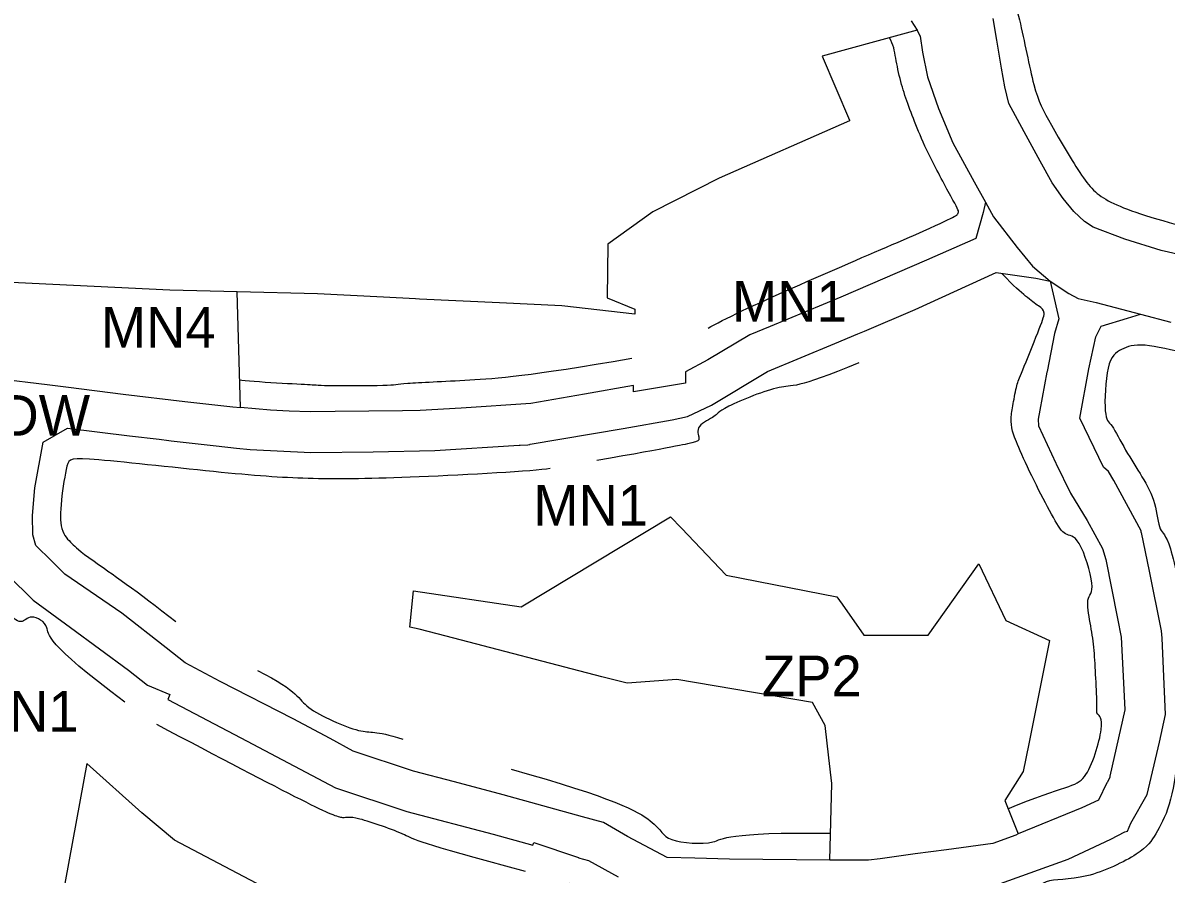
# Model space of a CAD drawing. Extents: x 7413438 to 7416393, y 5541665 to 5544118.
# Drawn here: x 7414274.3 to 7414442.9, y 5542946.8 to 5543072.4 of the extents above; entities that cross this region are included whole.
import ezdxf

# ---------------------------------------------------------------- set-up
doc = ezdxf.new("R2010")
doc.units = 0
for name, color, linetype in [('linie_rozgraniczajace', 7, 'Continuous'), ('linie_zabudowy_nieprzekraczalne', 7, 'Continuous'), ('oznaczenia_przeznaczen', 7, 'Continuous')]:
    doc.layers.add(name, color=color, linetype=linetype)

msp = doc.modelspace()

# ---------------------------------------------------------------- linework, layer by layer
at = {"layer": 'linie_rozgraniczajace'}
for p, q in [((7414405.28, 5543072.75), (7414406.15, 5543071.36)), ((7414417.91, 5543069.9), (7414417.38, 5543073.07)), ((7414403.99, 5543070.78), (7414392.16, 5543067.52)), ((7414406.15, 5543071.36), (7414403.99, 5543070.79)), ((7414403.99, 5543070.79), (7414403.99, 5543070.78)), ((7414406.15, 5543071.36), (7414406.58, 5543070.55)), ((7414406.58, 5543070.55), (7414406.61, 5543070.53)), ((7414406.61, 5543070.53), (7414406.61, 5543070.49)), ((7414406.61, 5543070.49), (7414406.93, 5543068.13)), ((7414418.6, 5543065.77), (7414417.91, 5543069.9)), ((7414392.16, 5543067.52), (7414396.16, 5543058.08)), ((7414406.93, 5543068.13), (7414407.67, 5543064.49)), ((7414419.07, 5543062.99), (7414418.6, 5543065.77)), ((7414407.67, 5543064.49), (7414409.33, 5543059.8)), ((7414419.68, 5543060.56), (7414419.07, 5543062.99)), ((7414421.92, 5543056.39), (7414419.68, 5543060.56)), ((7414409.33, 5543059.8), (7414411.44, 5543054.76)), ((7414396.16, 5543057.97), (7414376.95, 5543049.52)), ((7414396.16, 5543058.08), (7414396.16, 5543057.97)), ((7414424.31, 5543052.04), (7414421.92, 5543056.39)), ((7414411.44, 5543054.76), (7414414.55, 5543049.01)), ((7414426.09, 5543048.82), (7414424.31, 5543052.04)), ((7414376.95, 5543049.52), (7414367.18, 5543044.55)), ((7414414.55, 5543049.01), (7414416.22, 5543046)), ((7414427.67, 5543046.52), (7414426.09, 5543048.82)), ((7414429.28, 5543044.6), (7414427.67, 5543046.52)), ((7414416.22, 5543046), (7414415.92, 5543044.48)), ((7414416.22, 5543046), (7414417.42, 5543043.83)), ((7414367.18, 5543044.55), (7414360.55, 5543039.78)), ((7414415.92, 5543044.48), (7414414.81, 5543040.61)), ((7414417.42, 5543043.83), (7414420.89, 5543039.32)), ((7414430.85, 5543043.12), (7414429.28, 5543044.6)), ((7414432.11, 5543042.3), (7414430.85, 5543043.12)), ((7414436.79, 5543040.53), (7414432.11, 5543042.3)), ((7414360.55, 5543039.78), (7414360.46, 5543031.86)), ((7414414.81, 5543040.61), (7414407.55, 5543037.43)), ((7414442.16, 5543038.85), (7414436.79, 5543040.53)), ((7414420.89, 5543039.32), (7414423.15, 5543036.56)), ((7414468.63, 5543032.8), (7414442.16, 5543038.85)), ((7414407.55, 5543037.43), (7414394.92, 5543031.99)), ((7414423.15, 5543036.56), (7414425.77, 5543034.34)), ((7414295.95, 5543033.02), (7414248.57, 5543035.32)), ((7414405.89, 5543030.16), (7414417.81, 5543035.62)), ((7414417.81, 5543035.62), (7414423.64, 5543034.8)), ((7414423.64, 5543034.8), (7414425.77, 5543034.34)), ((7414305.88, 5543032.74), (7414295.95, 5543033.02)), ((7414425.77, 5543034.34), (7414426.05, 5543033.03)), ((7414425.77, 5543034.34), (7414428.53, 5543032.49)), ((7414426.05, 5543033.03), (7414427.05, 5543028.77)), ((7414306.35, 5543015.7), (7414305.88, 5543032.74)), ((7414317.73, 5543032.46), (7414305.88, 5543032.74)), ((7414327.47, 5543031.97), (7414317.73, 5543032.46)), ((7414332.2, 5543031.73), (7414327.47, 5543031.97)), ((7414332.77, 5543031.7), (7414332.2, 5543031.73)), ((7414344.56, 5543031.15), (7414332.77, 5543031.7)), ((7414360.46, 5543031.86), (7414364.53, 5543030.2)), ((7414394.92, 5543031.99), (7414384.49, 5543027.65)), ((7414428.53, 5543032.49), (7414429.89, 5543031.78)), ((7414429.89, 5543031.78), (7414432.56, 5543031.19)), ((7414353.77, 5543030.71), (7414344.56, 5543031.15)), ((7414364.51, 5543029.45), (7414353.77, 5543030.71)), ((7414364.53, 5543030.2), (7414364.51, 5543029.45)), ((7414398.39, 5543026.97), (7414405.89, 5543030.16)), ((7414432.56, 5543031.19), (7414439.11, 5543029.46)), ((7414427.05, 5543028.77), (7414426.42, 5543026.6)), ((7414433.31, 5543027.68), (7414437.19, 5543028.88)), ((7414437.19, 5543028.88), (7414439.11, 5543029.46)), ((7414439.11, 5543029.46), (7414443.55, 5543028.29)), ((7414381.5, 5543026.4), (7414375.3, 5543022.71)), ((7414384.49, 5543027.65), (7414381.5, 5543026.4)), ((7414394.04, 5543025.13), (7414397.42, 5543026.56)), ((7414397.42, 5543026.56), (7414398.39, 5543026.97)), ((7414426.42, 5543026.6), (7414425.33, 5543020.98)), ((7414432.53, 5543026.14), (7414433.31, 5543027.68)), ((7414384.11, 5543020.99), (7414394.04, 5543025.13)), ((7414431.5, 5543021.4), (7414432.53, 5543026.14)), ((7414375.3, 5543022.71), (7414372, 5543020.95)), ((7414430.13, 5543014.11), (7414431.5, 5543021.4)), ((7414267.9, 5543020.3), (7414277.85, 5543019.08)), ((7414372, 5543020.95), (7414372.01, 5543019.29)), ((7414375.84, 5543016.05), (7414384.11, 5543020.99)), ((7414425.3, 5543020.91), (7414424.25, 5543015.32)), ((7414425.33, 5543020.98), (7414425.3, 5543020.91)), ((7414277.85, 5543019.08), (7414281.03, 5543018.68)), ((7414281.03, 5543018.68), (7414289.06, 5543017.67)), ((7414364.31, 5543018.94), (7414357.11, 5543017.67)), ((7414364.32, 5543017.98), (7414364.31, 5543018.94)), ((7414372.01, 5543019.29), (7414364.32, 5543017.98)), ((7414289.06, 5543017.67), (7414298.17, 5543016.57)), ((7414298.17, 5543016.57), (7414305.23, 5543015.79)), ((7414349.18, 5543016.27), (7414338.91, 5543015.6)), ((7414357.11, 5543017.67), (7414349.18, 5543016.27)), ((7414305.23, 5543015.79), (7414306.35, 5543015.67)), ((7414310.82, 5543015.3), (7414306.35, 5543015.7)), ((7414306.35, 5543015.67), (7414306.35, 5543015.7)), ((7414313.55, 5543015.17), (7414310.82, 5543015.3)), ((7414316.65, 5543015.06), (7414313.55, 5543015.17)), ((7414320.33, 5543015.1), (7414316.65, 5543015.06)), ((7414330.25, 5543015.21), (7414320.33, 5543015.1)), ((7414332.88, 5543015.27), (7414330.25, 5543015.21)), ((7414338.91, 5543015.6), (7414332.88, 5543015.25)), ((7414332.88, 5543015.25), (7414332.88, 5543015.27)), ((7414372.31, 5543014.36), (7414375.84, 5543016.05)), ((7414424.25, 5543015.32), (7414424.01, 5543013.98)), ((7414362.81, 5543012.58), (7414370.02, 5543013.86)), ((7414370.02, 5543013.89), (7414372.31, 5543014.36)), ((7414370.02, 5543013.86), (7414370.02, 5543013.89)), ((7414424.01, 5543013.98), (7414424.08, 5543013.01)), ((7414424.08, 5543013.01), (7414426.59, 5543007.5)), ((7414433.62, 5543006.9), (7414430.13, 5543014.11)), ((7414277.25, 5543010.56), (7414280.84, 5543012.66)), ((7414280.84, 5543012.66), (7414290.02, 5543011.5)), ((7414290.02, 5543011.5), (7414294.36, 5543011)), ((7414349.1, 5543010.26), (7414362.81, 5543012.58)), ((7414276.05, 5543003.83), (7414277.25, 5543010.56)), ((7414294.36, 5543011), (7414295.81, 5543010.8)), ((7414295.81, 5543010.8), (7414296.17, 5543010.79)), ((7414296.17, 5543010.79), (7414302.76, 5543010.03)), ((7414302.76, 5543010.03), (7414305.79, 5543009.7)), ((7414305.79, 5543009.7), (7414307.82, 5543009.47)), ((7414307.82, 5543009.47), (7414316.73, 5543009.06)), ((7414335.04, 5543009.34), (7414347.45, 5543010.14)), ((7414347.45, 5543010.14), (7414347.63, 5543010.15)), ((7414347.63, 5543010.15), (7414348.76, 5543010.17)), ((7414348.76, 5543010.17), (7414349.06, 5543010.25)), ((7414349.06, 5543010.25), (7414349.1, 5543010.26)), ((7414316.73, 5543009.06), (7414325.96, 5543009.16)), ((7414325.96, 5543009.16), (7414335.04, 5543009.34)), ((7414426.59, 5543007.5), (7414426.63, 5543007.5)), ((7414426.63, 5543007.5), (7414426.64, 5543007.39)), ((7414426.64, 5543007.39), (7414428.77, 5543003.06)), ((7414434.38, 5543006.23), (7414433.62, 5543006.9)), ((7414435.16, 5543004.91), (7414434.38, 5543006.23)), ((7414439.18, 5542997.47), (7414435.16, 5543004.91)), ((7414275.72, 5542999.78), (7414276.05, 5543003.83)), ((7414428.77, 5543003.06), (7414431.21, 5542999)), ((7414275.73, 5542996.9), (7414275.72, 5542999.78)), ((7414347.76, 5542986.3), (7414369.81, 5542999.57)), ((7414369.81, 5542999.57), (7414371.41, 5542997.89)), ((7414371.41, 5542997.89), (7414371.41, 5542997.88)), ((7414371.41, 5542997.88), (7414378.01, 5542990.97)), ((7414431.21, 5542999), (7414433.49, 5542994.9)), ((7414276.17, 5542995.35), (7414275.73, 5542996.9)), ((7414439.22, 5542997.26), (7414439.18, 5542997.47)), ((7414439.23, 5542997.26), (7414439.22, 5542997.26)), ((7414440.45, 5542991.55), (7414439.23, 5542997.26)), ((7414278.48, 5542993.06), (7414276.17, 5542995.35)), ((7414433.49, 5542994.9), (7414433.99, 5542993.25)), ((7414280.46, 5542991.09), (7414278.48, 5542993.06)), ((7414407.77, 5542982.08), (7414415.24, 5542992.61)), ((7414415.24, 5542992.61), (7414419.22, 5542984.24)), ((7414433.99, 5542993.25), (7414435.71, 5542984.56)), ((7414272.07, 5542990.97), (7414275.78, 5542987.28)), ((7414282.32, 5542989.82), (7414280.46, 5542991.09)), ((7414378.01, 5542990.97), (7414394.32, 5542987.76)), ((7414442.18, 5542982.74), (7414440.45, 5542991.55)), ((7414288.88, 5542985.35), (7414282.32, 5542989.82)), ((7414331.35, 5542983.26), (7414331.89, 5542988.65)), ((7414331.89, 5542988.65), (7414347.76, 5542986.3)), ((7414394.32, 5542987.76), (7414395.08, 5542986.69)), ((7414275.78, 5542987.28), (7414281.31, 5542983.24)), ((7414395.08, 5542986.69), (7414398.31, 5542982.12)), ((7414295.39, 5542980.21), (7414288.88, 5542985.35)), ((7414419.22, 5542984.24), (7414425.7, 5542981.32)), ((7414435.71, 5542984.56), (7414436.25, 5542981.79)), ((7414281.31, 5542983.24), (7414289.84, 5542976.95)), ((7414332.73, 5542982.99), (7414331.35, 5542983.26)), ((7414336.69, 5542981.95), (7414332.73, 5542982.99)), ((7414442.27, 5542981.64), (7414442.18, 5542982.74)), ((7414359.65, 5542975.94), (7414336.69, 5542981.95)), ((7414398.31, 5542982.12), (7414404.1, 5542982.1)), ((7414404.1, 5542982.1), (7414407.77, 5542982.08)), ((7414425.7, 5542981.32), (7414422.62, 5542966.07)), ((7414436.25, 5542981.79), (7414436.65, 5542974.09)), ((7414442.5, 5542977.14), (7414442.27, 5542981.64)), ((7414298.19, 5542978), (7414295.39, 5542980.21)), ((7414303.35, 5542975.26), (7414298.19, 5542978)), ((7414289.84, 5542976.95), (7414292.65, 5542974.73)), ((7414363.38, 5542975.02), (7414359.65, 5542975.94)), ((7414442.79, 5542970.38), (7414442.5, 5542977.14)), ((7414292.65, 5542974.73), (7414295.95, 5542973.33)), ((7414314.12, 5542969.76), (7414303.35, 5542975.26)), ((7414370.71, 5542975.54), (7414363.38, 5542975.02)), ((7414390.75, 5542972.15), (7414370.71, 5542975.54)), ((7414436.65, 5542974.09), (7414436.81, 5542971.1)), ((7414295.95, 5542973.33), (7414295.65, 5542972.61)), ((7414295.65, 5542972.61), (7414306.4, 5542966.97)), ((7414392.59, 5542968.77), (7414390.75, 5542972.15)), ((7414436.81, 5542971.1), (7414434.6, 5542961.28)), ((7414319.59, 5542966.83), (7414314.12, 5542969.76)), ((7414441.89, 5542966.33), (7414442.79, 5542970.38)), ((7414393.15, 5542964.01), (7414392.59, 5542968.77)), ((7414306.4, 5542966.97), (7414320.37, 5542959.59)), ((7414322.99, 5542964.99), (7414319.59, 5542966.83)), ((7414422.62, 5542966.07), (7414421.79, 5542961.97)), ((7414440.09, 5542958.57), (7414441.89, 5542966.33)), ((7414331.89, 5542962.04), (7414322.99, 5542964.99)), ((7414393.59, 5542960.19), (7414393.15, 5542964.01)), ((7414283.71, 5542963.14), (7414278.97, 5542937.43)), ((7414283.72, 5542963.16), (7414283.71, 5542963.14)), ((7414291.83, 5542955.9), (7414283.72, 5542963.16)), ((7414337.93, 5542960.44), (7414331.89, 5542962.04)), ((7414421.79, 5542961.97), (7414419.09, 5542957.71)), ((7414434.57, 5542961.11), (7414434.17, 5542960.34)), ((7414434.6, 5542961.28), (7414434.57, 5542961.11)), ((7414320.37, 5542959.59), (7414330.91, 5542956.09)), ((7414345.12, 5542958.53), (7414337.93, 5542960.44)), ((7414393.28, 5542948.92), (7414393.59, 5542960.19)), ((7414434.13, 5542960.3), (7414432.91, 5542957.77)), ((7414434.17, 5542960.34), (7414434.13, 5542960.3)), ((7414356.83, 5542955.3), (7414345.12, 5542958.53)), ((7414419.09, 5542957.71), (7414421.08, 5542952.76)), ((7414432.91, 5542957.77), (7414430.43, 5542956.62)), ((7414437.68, 5542954.35), (7414440.09, 5542958.57)), ((7414296.63, 5542951.86), (7414291.83, 5542955.9)), ((7414330.91, 5542956.09), (7414343.62, 5542952.72)), ((7414430.43, 5542956.62), (7414421.08, 5542952.76)), ((7414359.89, 5542954.44), (7414356.83, 5542955.3)), ((7414363.46, 5542952.41), (7414359.89, 5542954.44)), ((7414437.17, 5542953.18), (7414437.68, 5542954.35)), ((7414343.62, 5542952.72), (7414349.5, 5542951.1)), ((7414369.27, 5542949.28), (7414363.46, 5542952.41)), ((7414420.7, 5542952.6), (7414417.32, 5542951.35)), ((7414421.08, 5542952.76), (7414420.7, 5542952.6)), ((7414434.74, 5542952.01), (7414436.8, 5542953.07)), ((7414436.8, 5542953.07), (7414437.17, 5542953.18)), ((7414296.63, 5542951.85), (7414296.63, 5542951.86)), ((7414325.17, 5542936.87), (7414296.63, 5542951.85)), ((7414349.5, 5542951.1), (7414349.64, 5542951.52)), ((7414349.64, 5542951.52), (7414356.23, 5542949.3)), ((7414410.49, 5542950.43), (7414405.88, 5542949.81)), ((7414417.32, 5542951.35), (7414410.49, 5542950.43)), ((7414428.42, 5542949.06), (7414434.74, 5542952.01)), ((7414356.23, 5542949.3), (7414356.21, 5542949.25)), ((7414356.21, 5542949.25), (7414357.68, 5542948.84)), ((7414357.68, 5542948.84), (7414362.05, 5542946.44)), ((7414373.39, 5542949.18), (7414369.27, 5542949.28)), ((7414378.5, 5542949.05), (7414373.39, 5542949.18)), ((7414393.27, 5542948.92), (7414378.5, 5542949.05)), ((7414393.28, 5542948.92), (7414393.27, 5542948.92)), ((7414396.5, 5542948.9), (7414393.28, 5542948.92)), ((7414398.98, 5542948.88), (7414396.5, 5542948.9)), ((7414400.69, 5542949.11), (7414398.98, 5542948.88)), ((7414405.88, 5542949.81), (7414400.69, 5542949.11)), ((7414418.45, 5542945.45), (7414428.42, 5542949.06))]:
    msp.add_line(p, q, dxfattribs=at)
at = {"layer": 'linie_zabudowy_nieprzekraczalne'}
for points in [[(7414431.95, 5543087.28), (7414424.23, 5543086.19), (7414420.06, 5543085.34), (7414419, 5543080.42), (7414421.28, 5543073.71), (7414423.39, 5543062.01), (7414425.39, 5543058.29), (7414430.81, 5543048.92), (7414433.87, 5543045.88), (7414444.69, 5543042.35), (7414474.63, 5543035.39), (7414481.89, 5543033.43), (7414483.16, 5543036.96), (7414485.08, 5543039.86), (7414490.96, 5543045.85), (7414497.7, 5543051.64), (7414500.63, 5543053.95), (7414503, 5543055.91), (7414505.09, 5543056.77), (7414509.77, 5543055.9), (7414530.22, 5543051.06), (7414537.37, 5543048.9), (7414539.27, 5543048.01), (7414540.33, 5543046.71), (7414543.6, 5543045.77), (7414547.8, 5543044.76), (7414549.47, 5543044.91), (7414562.64, 5543048.9), (7414579.93, 5543054.1), (7414600, 5543060.19), (7414616.25, 5543065.09), (7414646.94, 5543074.37), (7414667.99, 5543080.68), (7414683.48, 5543085.15), (7414703.27, 5543094.8), (7414711.92, 5543099.17), (7414719.64, 5543105.12), (7414735.49, 5543119.82), (7414750.36, 5543133.73), (7414756.76, 5543139.86), (7414758.13, 5543140.61), (7414759.94, 5543140.74), (7414761.63, 5543140.06), (7414763.36, 5543138.3), (7414765.4, 5543135.79), (7414765.75, 5543133.75), (7414763.94, 5543132.46), (7414737.28, 5543107.58), (7414725.35, 5543096.6), (7414718.45, 5543091.83), (7414705.59, 5543084.52), (7414694.22, 5543079.04), (7414682.4, 5543074.49), (7414654.76, 5543066.06), (7414598.61, 5543048.77), (7414574.71, 5543041.85)], [(7414375.32, 5543027.39), (7414379.54, 5543029.9), (7414410.74, 5543043.2), (7414412.55, 5543044.32), (7414412.05, 5543045.17), (7414407.88, 5543052.85), (7414406.1, 5543057.02), (7414404.74, 5543060.62), (7414403.7, 5543063.68), (7414402.94, 5543067.43), (7414402.69, 5543069.24), (7414402.07, 5543070.25)], [(7414419.52, 5542956.49), (7414428.17, 5542960.01), (7414431.05, 5542959.28), (7414434.05, 5542969.84), (7414432.49, 5542970.33), (7414432.74, 5542971.42), (7414432.47, 5542976.5), (7414432.27, 5542980.39), (7414431.73, 5542983.81), (7414430.93, 5542987.86), (7414432.67, 5542988.43), (7414429.95, 5542997.17), (7414427.96, 5542996.51), (7414426.48, 5542999), (7414423.72, 5543004.14), (7414421.09, 5543009.81), (7414420.09, 5543012.31), (7414419.96, 5543014.07), (7414420.27, 5543016.04), (7414420.89, 5543019.32), (7414421.3, 5543020.15), (7414424.29, 5543027.55), (7414425.2, 5543029.9), (7414424.2, 5543030.53), (7414422.29, 5543032), (7414420.51, 5543033.5), (7414418.67, 5543035.48)], [(7414508.57, 5543008.49), (7414498.05, 5543011.01), (7414482.82, 5543014.57), (7414466.45, 5543018.77), (7414466.58, 5543021.39), (7414454.91, 5543021.58), (7414446.03, 5543023.6), (7414439.09, 5543025.32), (7414436.2, 5543024.38), (7414434.02, 5543022.75), (7414433.67, 5543013.7), (7414434.74, 5543013.63), (7414436.82, 5543009.35), (7414439.42, 5543005.48), (7414441.42, 5543001.64), (7414441.84, 5542997.01), (7414443.29, 5542997.15), (7414446.06, 5542983.5), (7414446.66, 5542972.27), (7414444.62, 5542972.19), (7414444.71, 5542964.02), (7414443.51, 5542956.57), (7414441.21, 5542952.53), (7414439.68, 5542950.09), (7414430.8, 5542945.76), (7414424.13, 5542946.32), (7414423.85, 5542943.15), (7414419.34, 5542941.55), (7414419.25, 5542942.16), (7414410.29, 5542941.57), (7414410.19, 5542942.53), (7414398.73, 5542941.28), (7414399.01, 5542938.87), (7414386.65, 5542938.96), (7414386.72, 5542941.47), (7414376.67, 5542941.82), (7414376.65, 5542941.2), (7414372.17, 5542941.36), (7414372.04, 5542937.46), (7414368.78, 5542927.14), (7414366.7, 5542919.38), (7414363.5, 5542919.82), (7414362.16, 5542913.25), (7414361.63, 5542910.64), (7414365.18, 5542909.93), (7414363.25, 5542893.09), (7414363.14, 5542890.51), (7414361.23, 5542890.49), (7414360.59, 5542881.54), (7414370.8, 5542880.96), (7414377.49, 5542880.26)], [(7414364.1, 5543022.92), (7414348.65, 5543020.23), (7414339.68, 5543019.65), (7414329.31, 5543019.19), (7414329.33, 5543018.87), (7414317.5, 5543018.87), (7414317.28, 5543019.05), (7414311.04, 5543019.27), (7414306.18, 5543019.71), (7414306.17, 5543019.72)], [(7414397.55, 5543022.28), (7414388.1, 5543018.33), (7414387.47, 5543019.75), (7414376.5, 5543015.25), (7414376.82, 5543014.46), (7414373.33, 5543013.03), (7414374.21, 5543010.85), (7414373.69, 5543010.62), (7414370.31, 5543009.87), (7414358.94, 5543007.86)], [(7414289.31, 5542972.21), (7414277.42, 5542981.08), (7414278.75, 5542983.47), (7414275.17, 5542985.42), (7414274.19, 5542983.43), (7414271.84, 5542985.48), (7414268.18, 5542989.26), (7414266.98, 5542991.14), (7414265.83, 5542995.18), (7414265.61, 5542998.97), (7414265.8, 5543001.77), (7414266.89, 5543009.73), (7414266.45, 5543010.38), (7414242.28, 5543013.37)], [(7414352.03, 5543006.69), (7414349.67, 5543006.28), (7414330.03, 5543005.23), (7414316.72, 5543005.04), (7414305.67, 5543005.8), (7414281.63, 5543008.5), (7414280.81, 5543008.02), (7414279.83, 5543001.64), (7414279.68, 5542997.43), (7414281.59, 5542995.53), (7414282.96, 5542994.17), (7414291.13, 5542988.6), (7414296.84, 5542984.1)], [(7414240.16, 5542991.91), (7414241.96, 5542989.98), (7414242.1, 5542989.82), (7414246.63, 5542984.53), (7414246.67, 5542984.48), (7414246.87, 5542984.22), (7414247.05, 5542983.95), (7414247.22, 5542983.67), (7414247.37, 5542983.38), (7414247.5, 5542983.08), (7414247.55, 5542982.93), (7414248.56, 5542980.04), (7414250.04, 5542976.08), (7414250.09, 5542975.92), (7414254.4, 5542963.03), (7414259.61, 5542949.68), (7414263.34, 5542945.99), (7414265.03, 5542944.76), (7414265.22, 5542944.61), (7414265.47, 5542944.4), (7414265.7, 5542944.17), (7414265.75, 5542944.11), (7414275.66, 5542937.11), (7414275.67, 5542937.1), (7414288.45, 5542928.02), (7414300.93, 5542919.38), (7414300.97, 5542919.36), (7414301.01, 5542919.33), (7414318.78, 5542906.52), (7414342.51, 5542890.98), (7414348.64, 5542887.02), (7414349.3, 5542894.98), (7414350.7, 5542909.29), (7414351.82, 5542916.53), (7414354.71, 5542928.72), (7414357.45, 5542937.52), (7414359.24, 5542941.89), (7414358.67, 5542943.69), (7414356.12, 5542945.09), (7414354.88, 5542945.44)], [(7414308.9, 5542976.88), (7414315.15, 5542973.68), (7414314.41, 5542971.75), (7414325.49, 5542966.95), (7414326, 5542968.17), (7414330.29, 5542966.75)], [(7414348.38, 5542947.23), (7414332.06, 5542951.62), (7414332.21, 5542952.21), (7414322.41, 5542955.69), (7414321.95, 5542954.82), (7414318.45, 5542956.04), (7414303.36, 5542964), (7414294.02, 5542968.91)], [(7414346.29, 5542962.33), (7414361.46, 5542958.08), (7414368.61, 5542954.13), (7414368.46, 5542951.66), (7414377.45, 5542950.95), (7414377.75, 5542953.05), (7414393.34, 5542952.89)]]:
    msp.add_open_spline(points, degree=3, dxfattribs=at)

# ---------------------------------------------------------------- texts
at = {"layer": 'oznaczenia_przeznaczen'}
for s, p in [('MN1', (7414378.85, 5543028.34)), ('MN4', (7414285.77, 5543024.53)), ('KDW', (7414265.47, 5543011.52)), ('MN1', (7414349.55, 5542998.25)), ('ZP2', (7414383.27, 5542973.08)), ('MN1', (7414265.55, 5542967.86))]:
    msp.add_text(s, height=6, dxfattribs=at).set_placement(p)

doc.saveas('drawing.dxf')
